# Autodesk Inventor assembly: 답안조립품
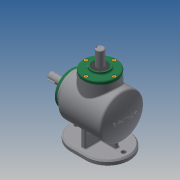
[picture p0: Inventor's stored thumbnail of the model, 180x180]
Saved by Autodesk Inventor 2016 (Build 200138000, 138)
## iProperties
Created: 2016-04
Part Number: 답안조립품
Document SubType Name: Assembly
Designer: Administrator
Author: Administrator
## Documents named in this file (14)
- D:\460408V1003\답안조립품.iam
- D:\460408V1003\본체.ipt
- D:\460408V1003\메인 축.ipt
- 메인 축.ipt
- D:\460408V1003\메인 베벨기어.ipt
- D:\460408V1003\키 5x5.ipt
- D:\460408V1003\커버.ipt
- D:\460408V1003\베어링 6203.ipt
- D:\460408V1003\오일실 17 32 8.ipt
- D:\460408V1003\서브 축.ipt
- 서브 축.ipt
- D:\460408V1003\서브 베벨기어.ipt
- D:\460408V1003\키 4x4.ipt
- D:\460408V1003\M4.ipt
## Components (8 placed, 1 different names)
1. M4:1
2. M4:2
3. M4:3
4. M4:4
5. M4:5
6. M4:6
7. M4:7
8. M4:8
